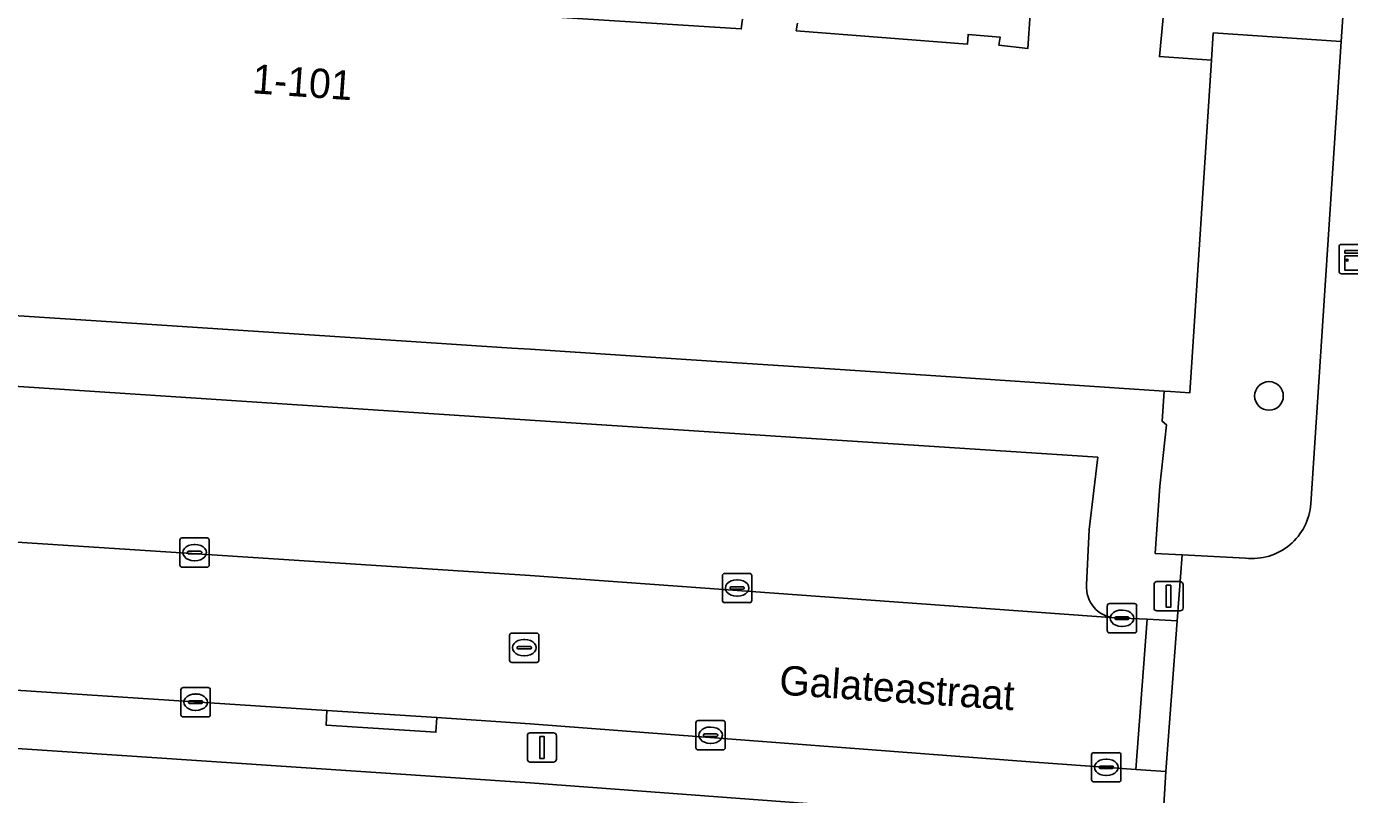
# Model space of a CAD drawing. Extents: x 161848 to 162726, y 385382 to 386521.
# Drawn here: x 161982.81 to 162027.96, y 385969.08 to 385995.3 of the extents above; entities that cross this region are included whole.
import ezdxf

# ---------------------------------------------------------------- set-up
doc = ezdxf.new("R2010")
doc.units = 0
for name, color, linetype in [('IMGEO_Boom', 7, 'Continuous'), ('IMGEO_Erf', 7, 'Continuous'), ('IMGEO_Groenvoorziening', 7, 'Continuous'), ('IMGEO_Kast', 7, 'Continuous'), ('IMGEO_Kolk', 7, 'Continuous'), ('IMGEO_Lichtmast', 7, 'Continuous'), ('IMGEO_Openbare_ruimte_label', 7, 'Continuous'), ('IMGEO_Pand', 7, 'Continuous'), ('IMGEO_Pand_nummerreeks', 7, 'Continuous'), ('IMGEO_Pand_overbouw', 7, 'Continuous'), ('IMGEO_Parkeervlak_open', 7, 'Continuous'), ('IMGEO_Rijbaan_lokaal_open', 7, 'Continuous'), ('IMGEO_Rioolput', 7, 'Continuous'), ('IMGEO_Voetpad_open', 7, 'Continuous')]:
    doc.layers.add(name, color=color, linetype=linetype)

msp = doc.modelspace()

# ---------------------------------------------------------------- linework, layer by layer
at = {"layer": 'IMGEO_Boom'}
msp.add_circle((162025.216, 385982.686), 0.489, dxfattribs=at)
at = {"layer": 'IMGEO_Erf'}
msp.add_lwpolyline([(162019.07, 385968.054), (162000, 385969.481), (161967.542, 385971.654)], dxfattribs=at)
at = {"layer": 'IMGEO_Groenvoorziening'}
for points in [[(162027.676, 385994.782), (162023.315, 385995.076), (162023.255, 385994.15), (162022.515, 385982.796), (162021.851, 385982.84), (162021.635, 385982.854), (162021.573, 385981.819), (162021.713, 385981.701), (162021.488, 385979.608), (162021.333, 385977.308), (162022.248, 385977.26), (162024.417, 385977.147)], [(162026.642, 385979.005), (162027.676, 385994.782)]]:
    msp.add_lwpolyline(points, dxfattribs=at)
msp.add_arc((162024.635, 385979.147), 2.012, 263.7742, 355.9534, dxfattribs=at)
at = {"layer": 'IMGEO_Kast'}
for p, q in [((162027.606, 385986.933), (162027.606, 385987.774)), ((162027.606, 385987.774), (162027.606, 385986.933)), ((162027.681, 385987.858), (162028.522, 385987.858)), ((162028.522, 385987.858), (162027.681, 385987.858)), ((162028.531, 385986.858), (162027.69, 385986.858)), ((162027.69, 385986.858), (162028.531, 385986.858))]:
    msp.add_line(p, q, dxfattribs=at)
for points in [[(162027.801, 385987.648), (162028.401, 385987.648), (162028.401, 385987.563), (162027.801, 385987.563), (162027.801, 385987.648)], [(162027.801, 385987.473), (162028.401, 385987.473), (162028.401, 385986.984), (162027.801, 385986.984), (162027.801, 385987.473)]]:
    msp.add_lwpolyline(points, dxfattribs=at)
msp.add_circle((162027.885, 385987.322), 0.0377, dxfattribs=at)
for centre, start, end in [((162027.684, 385987.78), 92.4484, 184.2845), ((162027.684, 385987.78), 92.4484, 184.2845), ((162027.684, 385986.936), 182.4484, 274.2845), ((162027.684, 385986.936), 182.4484, 274.2845)]:
    msp.add_arc(centre, 0.0779, start, end, dxfattribs=at)
at = {"layer": 'IMGEO_Kolk'}
for p, q in [((161988.053, 385976.912), (161988.053, 385977.764)), ((161988.128, 385977.838), (161988.98, 385977.838)), ((161988.541, 385977.618), (161988.566, 385977.618)), ((161989.054, 385977.764), (161989.054, 385976.912)), ((161988.312, 385977.332), (161988.312, 385977.344)), ((161988.75, 385977.295), (161988.352, 385977.295)), ((161988.355, 385977.381), (161988.753, 385977.381)), ((161988.796, 385977.344), (161988.796, 385977.332)), ((161988.98, 385976.838), (161988.128, 385976.838)), ((161988.564, 385977.058), (161988.539, 385977.058)), ((162006.565, 385975.703), (162006.565, 385976.555)), ((162006.64, 385976.629), (162007.492, 385976.629)), ((162007.053, 385976.409), (162007.078, 385976.409)), ((162007.566, 385976.555), (162007.566, 385975.703)), ((162006.824, 385976.123), (162006.824, 385976.135)), ((162007.262, 385976.086), (162006.864, 385976.086)), ((162006.867, 385976.172), (162007.265, 385976.172)), ((162007.076, 385975.849), (162007.051, 385975.849)), ((162007.308, 385976.135), (162007.308, 385976.123)), ((162007.492, 385975.629), (162006.64, 385975.629)), ((162019.699, 385974.671), (162019.699, 385975.523)), ((162019.774, 385975.597), (162020.626, 385975.597)), ((162020.187, 385975.377), (162020.212, 385975.377)), ((162020.7, 385975.523), (162020.7, 385974.671)), ((162019.958, 385975.091), (162019.958, 385975.103)), ((162020.396, 385975.054), (162019.998, 385975.054)), ((162020.001, 385975.14), (162020.399, 385975.14)), ((162020.442, 385975.103), (162020.442, 385975.091)), ((162020.626, 385974.597), (162019.774, 385974.597)), ((162020.21, 385974.817), (162020.185, 385974.817)), ((161988.088, 385971.805), (161988.088, 385972.657)), ((161988.163, 385972.731), (161989.015, 385972.731)), ((161989.089, 385972.657), (161989.089, 385971.805)), ((161988.347, 385972.225), (161988.347, 385972.237)), ((161988.39, 385972.274), (161988.788, 385972.274)), ((161988.576, 385972.511), (161988.601, 385972.511)), ((161988.831, 385972.237), (161988.831, 385972.225)), ((161988.785, 385972.188), (161988.387, 385972.188)), ((161988.599, 385971.951), (161988.574, 385971.951)), ((161989.015, 385971.731), (161988.163, 385971.731)), ((162005.661, 385970.677), (162005.661, 385971.529)), ((162005.736, 385971.603), (162006.588, 385971.603)), ((162006.149, 385971.383), (162006.174, 385971.383)), ((162006.662, 385971.529), (162006.662, 385970.677)), ((162005.92, 385971.097), (162005.92, 385971.109)), ((162006.358, 385971.06), (162005.96, 385971.06)), ((162005.963, 385971.146), (162006.361, 385971.146)), ((162006.404, 385971.109), (162006.404, 385971.097)), ((162006.588, 385970.603), (162005.736, 385970.603)), ((162006.172, 385970.823), (162006.147, 385970.823)), ((162019.164, 385969.582), (162019.164, 385970.434)), ((162019.239, 385970.508), (162020.091, 385970.508)), ((162020.165, 385970.434), (162020.165, 385969.582)), ((162019.423, 385970.002), (162019.423, 385970.014)), ((162019.861, 385969.965), (162019.463, 385969.965)), ((162019.466, 385970.051), (162019.864, 385970.051)), ((162019.652, 385970.288), (162019.677, 385970.288)), ((162019.907, 385970.014), (162019.907, 385970.002)), ((162020.091, 385969.508), (162019.239, 385969.508)), ((162019.675, 385969.728), (162019.65, 385969.728))]:
    msp.add_line(p, q, dxfattribs=at)
for points in [[(161988.053, 385976.912), (161988.053, 385977.764)], [(161988.128, 385977.838), (161988.98, 385977.838)], [(161989.054, 385977.764), (161989.054, 385976.912)], [(161988.98, 385976.838), (161988.128, 385976.838)], [(162006.565, 385975.703), (162006.565, 385976.555)], [(162006.64, 385976.629), (162007.492, 385976.629)], [(162007.566, 385976.555), (162007.566, 385975.703)], [(162007.492, 385975.629), (162006.64, 385975.629)], [(162019.699, 385974.671), (162019.699, 385975.523)], [(162019.774, 385975.597), (162020.626, 385975.597)], [(162020.7, 385975.523), (162020.7, 385974.671)], [(162020.626, 385974.597), (162019.774, 385974.597)], [(161988.088, 385971.805), (161988.088, 385972.657)], [(161988.163, 385972.731), (161989.015, 385972.731)], [(161989.089, 385972.657), (161989.089, 385971.805)], [(161989.015, 385971.731), (161988.163, 385971.731)], [(162005.661, 385970.677), (162005.661, 385971.529)], [(162005.736, 385971.603), (162006.588, 385971.603)], [(162006.662, 385971.529), (162006.662, 385970.677)], [(162006.588, 385970.603), (162005.736, 385970.603)], [(162019.164, 385969.582), (162019.164, 385970.434)], [(162019.239, 385970.508), (162020.091, 385970.508)], [(162020.165, 385970.434), (162020.165, 385969.582)], [(162020.091, 385969.508), (162019.239, 385969.508)]]:
    msp.add_lwpolyline(points, dxfattribs=at)
for centre, radius, start, end in [((161988.13, 385977.762), 0.0765, 91.552, 178.448), ((161988.13, 385977.762), 0.0765, 91.552, 178.448), ((161988.978, 385977.762), 0.0765, 1.552, 88.448), ((161988.978, 385977.762), 0.0765, 1.552, 88.448), ((161988.352, 385977.341), 0.0403, 85.8775, 175.7526), ((161988.349, 385977.331), 0.0366, 178.938, 274.7102), ((161988.753, 385977.338), 0.043, 264.8664, 352.4533), ((161988.757, 385977.343), 0.0386, 1.7309, 96.639), ((161988.13, 385976.914), 0.0765, 181.552, 268.448), ((161988.13, 385976.914), 0.0765, 181.552, 268.448), ((161988.978, 385976.914), 0.0765, 271.552, 358.448), ((161988.978, 385976.914), 0.0765, 271.552, 358.448), ((162006.642, 385976.553), 0.0765, 91.552, 178.448), ((162006.642, 385976.553), 0.0765, 91.552, 178.448), ((162007.49, 385976.553), 0.0765, 1.552, 88.448), ((162007.49, 385976.553), 0.0765, 1.552, 88.448), ((162006.864, 385976.132), 0.0403, 85.8775, 175.7526), ((162006.861, 385976.122), 0.0366, 178.938, 274.7102), ((162007.265, 385976.129), 0.043, 264.8664, 352.4533), ((162007.269, 385976.134), 0.0386, 1.7309, 96.639), ((162006.642, 385975.705), 0.0765, 181.552, 268.448), ((162006.642, 385975.705), 0.0765, 181.552, 268.448), ((162007.49, 385975.705), 0.0765, 271.552, 358.448), ((162007.49, 385975.705), 0.0765, 271.552, 358.448), ((162019.776, 385975.521), 0.0765, 91.552, 178.448), ((162019.776, 385975.521), 0.0765, 91.552, 178.448), ((162020.624, 385975.521), 0.0765, 1.552, 88.448), ((162020.624, 385975.521), 0.0765, 1.552, 88.448), ((162019.998, 385975.1), 0.0403, 85.8775, 175.7526), ((162019.995, 385975.09), 0.0366, 178.938, 274.7102), ((162020.399, 385975.097), 0.043, 264.8664, 352.4533), ((162020.403, 385975.102), 0.0386, 1.7309, 96.639), ((162019.776, 385974.673), 0.0765, 181.552, 268.448), ((162019.776, 385974.673), 0.0765, 181.552, 268.448), ((162020.624, 385974.673), 0.0765, 271.552, 358.448), ((162020.624, 385974.673), 0.0765, 271.552, 358.448), ((161988.165, 385972.655), 0.0765, 91.552, 178.448), ((161988.165, 385972.655), 0.0765, 91.552, 178.448), ((161989.013, 385972.655), 0.0765, 1.552, 88.448), ((161989.013, 385972.655), 0.0765, 1.552, 88.448), ((161988.387, 385972.234), 0.0403, 85.8775, 175.7526), ((161988.384, 385972.224), 0.0366, 178.938, 274.7102), ((161988.788, 385972.231), 0.043, 264.8664, 352.4533), ((161988.792, 385972.236), 0.0386, 1.7309, 96.639), ((161988.165, 385971.807), 0.0765, 181.552, 268.448), ((161988.165, 385971.807), 0.0765, 181.552, 268.448), ((161989.013, 385971.807), 0.0765, 271.552, 358.448), ((161989.013, 385971.807), 0.0765, 271.552, 358.448), ((162005.738, 385971.527), 0.0765, 91.552, 178.448), ((162005.738, 385971.527), 0.0765, 91.552, 178.448), ((162006.586, 385971.527), 0.0765, 1.552, 88.448), ((162006.586, 385971.527), 0.0765, 1.552, 88.448), ((162005.96, 385971.106), 0.0403, 85.8775, 175.7526), ((162005.957, 385971.096), 0.0366, 178.938, 274.7102), ((162006.361, 385971.103), 0.043, 264.8664, 352.4533), ((162006.365, 385971.108), 0.0386, 1.7309, 96.639), ((162005.738, 385970.679), 0.0765, 181.552, 268.448), ((162005.738, 385970.679), 0.0765, 181.552, 268.448), ((162006.586, 385970.679), 0.0765, 271.552, 358.448), ((162006.586, 385970.679), 0.0765, 271.552, 358.448), ((162019.241, 385970.432), 0.0765, 91.552, 178.448), ((162019.241, 385970.432), 0.0765, 91.552, 178.448), ((162020.089, 385970.432), 0.0765, 1.552, 88.448), ((162020.089, 385970.432), 0.0765, 1.552, 88.448), ((162019.463, 385970.011), 0.0403, 85.8775, 175.7526), ((162019.46, 385970.001), 0.0366, 178.938, 274.7102), ((162019.864, 385970.008), 0.043, 264.8664, 352.4533), ((162019.868, 385970.013), 0.0386, 1.7309, 96.639), ((162019.241, 385969.584), 0.0765, 181.552, 268.448), ((162019.241, 385969.584), 0.0765, 181.552, 268.448), ((162020.089, 385969.584), 0.0765, 271.552, 358.448), ((162020.089, 385969.584), 0.0765, 271.552, 358.448)]:
    msp.add_arc(centre, radius, start, end, dxfattribs=at)
for centre, major_axis, ratio, start_param, end_param in [((161988.54, 385977.338), (-0.387, 0.002), 0.722429, 4.712389, 7.853982), ((161988.565, 385977.338), (-0.39, 0.002), 0.717154, 1.570796, 4.712389), ((162007.052, 385976.129), (-0.387, 0.002), 0.722429, 4.712389, 7.853982), ((162007.077, 385976.129), (-0.39, 0.002), 0.717154, 1.570796, 4.712389), ((162020.186, 385975.097), (-0.387, 0.002), 0.722429, 4.712389, 7.853982), ((162020.211, 385975.097), (-0.39, 0.002), 0.717154, 1.570796, 4.712389), ((161988.575, 385972.231), (-0.387, 0.002), 0.722429, 4.712389, 7.853982), ((161988.6, 385972.231), (-0.39, 0.002), 0.717154, 1.570796, 4.712389), ((162006.148, 385971.103), (-0.387, 0.002), 0.722429, 4.712389, 7.853982), ((162006.173, 385971.103), (-0.39, 0.002), 0.717154, 1.570796, 4.712389), ((162019.651, 385970.008), (-0.387, 0.002), 0.722429, 4.712389, 7.853982), ((162019.676, 385970.008), (-0.39, 0.002), 0.717154, 1.570796, 4.712389)]:
    msp.add_ellipse(centre, major_axis=major_axis, ratio=ratio, start_param=start_param, end_param=end_param, dxfattribs=at)
at = {"layer": 'IMGEO_Lichtmast'}
for p, q in [((162021.392, 385976.348), (162022.182, 385976.348)), ((162022.182, 385976.348), (162021.392, 385976.348)), ((162021.292, 385975.448), (162021.292, 385976.248)), ((162021.292, 385976.248), (162021.292, 385975.448)), ((162022.282, 385976.248), (162022.282, 385975.448)), ((162022.282, 385975.448), (162022.282, 385976.248)), ((162022.182, 385975.348), (162021.392, 385975.348)), ((162021.392, 385975.348), (162022.182, 385975.348)), ((161999.908, 385970.287), (161999.908, 385971.087)), ((161999.908, 385971.087), (161999.908, 385970.287)), ((162000.008, 385971.187), (162000.798, 385971.187)), ((162000.798, 385971.187), (162000.008, 385971.187)), ((162000.898, 385971.087), (162000.898, 385970.287)), ((162000.898, 385970.287), (162000.898, 385971.087)), ((162000.798, 385970.187), (162000.008, 385970.187)), ((162000.008, 385970.187), (162000.798, 385970.187))]:
    msp.add_line(p, q, dxfattribs=at)
for points in [[(162021.712, 385976.223), (162021.862, 385976.223), (162021.862, 385975.473), (162021.712, 385975.473), (162021.712, 385976.223)], [(162000.328, 385971.062), (162000.478, 385971.062), (162000.478, 385970.312), (162000.328, 385970.312), (162000.328, 385971.062)]]:
    msp.add_lwpolyline(points, dxfattribs=at)
for centre, start, end in [((162021.392, 385976.248), 90, 180), ((162021.392, 385976.248), 90, 180), ((162022.182, 385976.248), 0, 90), ((162022.182, 385976.248), 360, 90), ((162021.392, 385975.448), 180, 270), ((162021.392, 385975.448), 180, 270), ((162022.182, 385975.448), 270, 0), ((162022.182, 385975.448), 270, 0), ((162000.008, 385971.087), 90, 180), ((162000.008, 385971.087), 90, 180), ((162000.798, 385971.087), 0, 90), ((162000.798, 385971.087), 360, 90), ((162000.008, 385970.287), 180, 270), ((162000.008, 385970.287), 180, 270), ((162000.798, 385970.287), 270, 0), ((162000.798, 385970.287), 270, 0)]:
    msp.add_arc(centre, 0.1, start, end, dxfattribs=at)
at = {"layer": 'IMGEO_Pand'}
for points in [[(161981.32, 385985.503), (161985.194, 385985.252), (161988.817, 385985.014), (161995.767, 385984.557), (161999.382, 385984.32), (162000, 385984.279), (162003.261, 385984.064), (162006.884, 385983.826), (162010.748, 385983.571), (162014.36, 385983.333), (162018.24, 385983.078), (162021.635, 385982.854), (162021.851, 385982.84), (162022.515, 385982.796), (162023.255, 385994.15), (162021.474, 385994.271), (162021.702, 385996.701)], [(162017.15, 385996.928), (162016.988, 385994.549), (162016.002, 385994.654), (162016.04, 385994.937), (162014.945, 385995.026), (162014.93, 385994.697), (162009.081, 385995.149), (162009.125, 385995.413)], [(162007.249, 385995.546), (162007.206, 385995.217), (162000, 385995.676)]]:
    msp.add_lwpolyline(points, dxfattribs=at)
at = {"layer": 'IMGEO_Pand_overbouw'}
for points in [[(162009.125, 385995.413), (162009.081, 385995.149), (162014.93, 385994.697), (162014.945, 385995.026), (162016.04, 385994.937), (162016.002, 385994.654), (162016.988, 385994.549), (162017.15, 385996.928)], [(162000, 385995.676), (162007.206, 385995.217), (162007.249, 385995.546)]]:
    msp.add_lwpolyline(points, dxfattribs=at)
at = {"layer": 'IMGEO_Parkeervlak_open'}
for points in [[(162018.992, 385976.237), (162019.085, 385978.123), (162019.373, 385980.593), (162000, 385981.864), (161969.587, 385983.859), (161969.352, 385979.563)], [(161968.288, 385978.612), (162000, 385976.558), (162019.954, 385975.106)]]:
    msp.add_lwpolyline(points, dxfattribs=at)
msp.add_arc((162020.039, 385976.153), 1.05, 175.385, 265.3823, dxfattribs=at)
at = {"layer": 'IMGEO_Rijbaan_lokaal_open'}
for points in [[(162021.063, 385975.065), (162019.954, 385975.106), (162000, 385976.558), (161968.288, 385978.612), (161958.167, 385979.276), (161957.537, 385969.453), (161962.469, 385969.192)], [(161968.352, 385973.563), (161993.069, 385971.948), (161996.821, 385971.703), (162000, 385971.495), (162017.211, 385970.186), (162020.667, 385969.935), (162021.063, 385975.065)]]:
    msp.add_lwpolyline(points, dxfattribs=at)
msp.add_lwpolyline([(162020.667, 385969.935), (162021.69, 385969.861), (162022.086, 385975.013), (162021.063, 385975.065)], close=True, dxfattribs=at)
at = {"layer": 'IMGEO_Rioolput'}
for p, q in [((161999.303, 385973.665), (161999.303, 385974.517)), ((161999.378, 385974.591), (162000.23, 385974.591)), ((162000.304, 385974.517), (162000.304, 385973.665)), ((161999.562, 385974.085), (161999.562, 385974.097)), ((162000, 385974.048), (161999.602, 385974.048)), ((161999.605, 385974.134), (162000.003, 385974.134)), ((161999.791, 385974.371), (161999.816, 385974.371)), ((162000.046, 385974.097), (162000.046, 385974.085)), ((162000.23, 385973.591), (161999.378, 385973.591)), ((161999.814, 385973.811), (161999.789, 385973.811))]:
    msp.add_line(p, q, dxfattribs=at)
for points in [[(161999.303, 385973.665), (161999.303, 385974.517)], [(161999.378, 385974.591), (162000.23, 385974.591)], [(162000.304, 385974.517), (162000.304, 385973.665)], [(162000.23, 385973.591), (161999.378, 385973.591)]]:
    msp.add_lwpolyline(points, dxfattribs=at)
for centre, radius, start, end in [((161999.38, 385974.515), 0.0765, 91.552, 178.448), ((161999.38, 385974.515), 0.0765, 91.552, 178.448), ((162000.228, 385974.515), 0.0765, 1.552, 88.448), ((162000.228, 385974.515), 0.0765, 1.552, 88.448), ((161999.602, 385974.094), 0.0403, 85.8775, 175.7526), ((161999.599, 385974.084), 0.0366, 178.938, 274.7102), ((162000.003, 385974.091), 0.043, 264.8664, 352.4533), ((162000.007, 385974.096), 0.0386, 1.7309, 96.639), ((161999.38, 385973.667), 0.0765, 181.552, 268.448), ((161999.38, 385973.667), 0.0765, 181.552, 268.448), ((162000.228, 385973.667), 0.0765, 271.552, 358.448), ((162000.228, 385973.667), 0.0765, 271.552, 358.448)]:
    msp.add_arc(centre, radius, start, end, dxfattribs=at)
for centre, major_axis, ratio, start_param, end_param in [((161999.79, 385974.091), (-0.387, 0.002), 0.722429, 4.712389, 7.853982), ((161999.815, 385974.091), (-0.39, 0.002), 0.717154, 1.570796, 4.712389)]:
    msp.add_ellipse(centre, major_axis=major_axis, ratio=ratio, start_param=start_param, end_param=end_param, dxfattribs=at)
at = {"layer": 'IMGEO_Voetpad_open'}
for points in [[(162027.833, 385997.182), (162027.776, 385996.309), (162027.676, 385994.782), (162026.642, 385979.005)], [(162009.125, 385995.413), (162009.081, 385995.149), (162014.93, 385994.697), (162014.945, 385995.026), (162016.04, 385994.937), (162016.002, 385994.654), (162016.988, 385994.549), (162017.15, 385996.928)], [(162000, 385995.676), (162007.206, 385995.217), (162007.249, 385995.546)], [(162014.36, 385983.333), (162010.748, 385983.571), (162006.884, 385983.826), (162003.261, 385984.064), (162000, 385984.279), (161999.382, 385984.32), (161995.767, 385984.557), (161988.817, 385985.014), (161985.194, 385985.252), (161981.32, 385985.503), (161977.687, 385985.739), (161973.846, 385985.988), (161970.224, 385986.223), (161969.98, 385986.239), (161969.601, 385986.263), (161969.587, 385983.859), (162000, 385981.864), (162019.373, 385980.593), (162019.085, 385978.123), (162018.992, 385976.237)], [(162019.954, 385975.106), (162021.063, 385975.065), (162022.086, 385975.013), (162022.248, 385977.26), (162021.333, 385977.308), (162021.488, 385979.608), (162021.713, 385981.701), (162021.573, 385981.819), (162021.635, 385982.854), (162018.24, 385983.078), (162014.36, 385983.333)], [(162024.417, 385977.147), (162022.248, 385977.26), (162022.086, 385975.013), (162021.69, 385969.861), (162021.428, 385965.253), (162016.387, 385890.314), (162015.467, 385876.641), (162015.241, 385876.631), (162014.909, 385871.646), (162019.923, 385871.211), (162019.65, 385867.208), (162019.318, 385862.334), (162019.302, 385862.103), (162016.633, 385862.282), (162016.617, 385862.075), (162014.406, 385862.215), (162014.297, 385860.555), (162019.019, 385860.238), (162018.504, 385849.346)], [(162000, 385971.495), (161996.821, 385971.703), (161996.789, 385971.205), (161993.037, 385971.45), (161993.069, 385971.948), (161968.352, 385973.563)], [(161967.542, 385971.654), (162000, 385969.481), (162019.07, 385968.054)], [(162021.428, 385965.253), (162021.69, 385969.861), (162020.667, 385969.935), (162017.211, 385970.186), (162000, 385971.495)]]:
    msp.add_lwpolyline(points, dxfattribs=at)
for points in [[(162027.776, 385996.309), (162025.594, 385996.456), (162021.702, 385996.701), (162021.474, 385994.271), (162023.255, 385994.15), (162023.315, 385995.076), (162027.676, 385994.782)], [(161996.821, 385971.703), (161993.069, 385971.948), (161993.037, 385971.45), (161996.789, 385971.205)]]:
    msp.add_lwpolyline(points, close=True, dxfattribs=at)
for centre, radius, start, end in [((162024.635, 385979.147), 2.012, 263.7742, 355.9534), ((162020.039, 385976.153), 1.05, 175.385, 265.3823)]:
    msp.add_arc(centre, radius, start, end, dxfattribs=at)

# ---------------------------------------------------------------- texts
at = {"layer": 'IMGEO_Openbare_ruimte_label'}
msp.add_text('Galateastraat', height=1, rotation=356.1593, dxfattribs=at).set_placement((162008.483, 385972.493))
at = {"layer": 'IMGEO_Pand_nummerreeks'}
msp.add_text('1-101', height=1, rotation=355.9435, dxfattribs=at).set_placement((161990.497, 385993.02))

doc.saveas('drawing.dxf')
